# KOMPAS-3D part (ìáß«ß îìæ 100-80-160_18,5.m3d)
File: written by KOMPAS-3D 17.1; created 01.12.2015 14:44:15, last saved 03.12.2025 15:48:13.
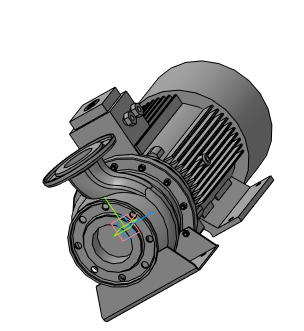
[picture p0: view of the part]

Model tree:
1. Операция без истории:4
